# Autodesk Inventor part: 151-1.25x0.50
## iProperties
Created: 2007-07
Part Number: 151-1.25x0.50
Document SubType Name: Modeling
Designer: btaylor
Density: 1 g/cm^3
Author: btaylor
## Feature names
1. Loft1
2. Extrusion4
3. Extrusion2
4. Fillet1
5. Fillet2
6. Extrusion5
7. Extrusion6
8. Chamfer1
9. Chamfer2
10. Fillet3
11. Fillet4
12. Loft2
13. Fillet5
14. Fillet6
